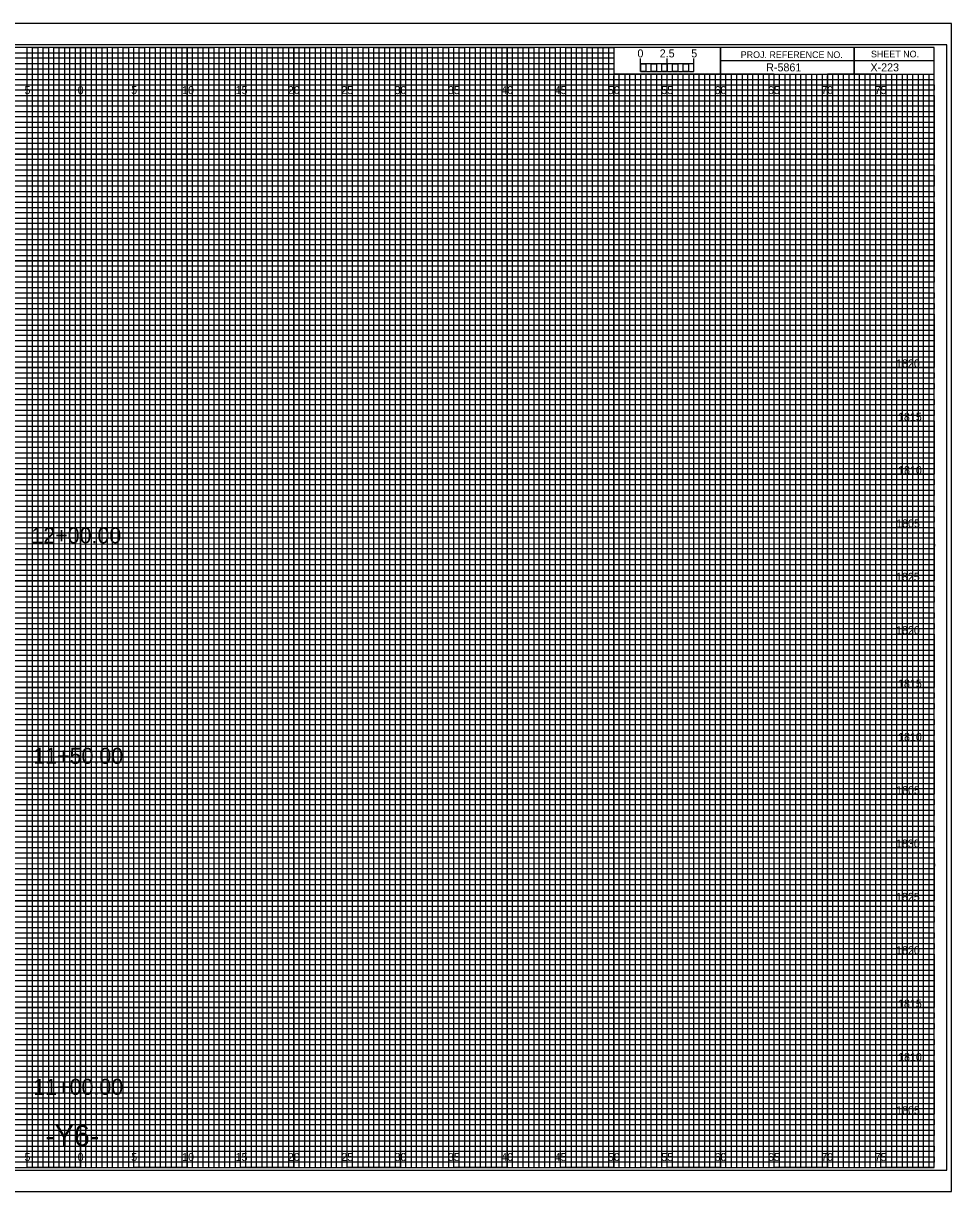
# Model space of a CAD drawing. Extents: x -7 to 392, y -2 to 440.
# Drawn here: x 74.6 to 161.6, y -2.3 to 107.3 of the extents above; entities that cross this region are included whole.
import ezdxf

# ---------------------------------------------------------------- set-up
doc = ezdxf.new("R2010")
doc.units = 0
for name, color, linetype in [('Prop Grid Mask', 7, 'Continuous'), ('Prop XS Alignment Label', 7, 'Continuous'), ('Prop XS Bar Scale Labels', 7, 'Continuous'), ('Prop XS Elevation Labels', 7, 'Continuous'), ('Prop XS Project Number', 7, 'Continuous'), ('Prop XS Sheet Number', 7, 'Continuous'), ('Prop XS Station Labels', 7, 'Continuous'), ('Sheet Cross Section CELL', 7, 'Continuous'), ('Sheet Cross Section Grid Major CELL', 7, 'Continuous'), ('Sheet Cross Section Grid Middle CELL', 7, 'Continuous'), ('Sheet Cross Section Grid Minor 1 CELL', 7, 'Continuous'), ('Sheet Cross Section Grid Minor 2 CELL', 7, 'Continuous'), ('Sheet Cross Section Scale CELL', 7, 'Continuous'), ('Sheet Cutting Line CELL', 7, 'Continuous'), ('Sheet DOT Grid CELL', 7, 'Continuous'), ('Sheet Plot Border Inside CELL', 7, 'Continuous'), ('Sheet Plot Border Outside CELL', 7, 'Continuous')]:
    doc.layers.add(name, color=color, linetype=linetype)

msp = doc.modelspace()

# ---------------------------------------------------------------- linework, layer by layer
at = {"layer": 'Sheet Cross Section CELL'}
for p, q in [((152.5, 105), (152.5, 102.5)), ((152.5, 102.5), (152.5, 105)), ((160, 103.75), (140, 103.75)), ((140, 103.75), (140, 102.5)), ((140, 102.5), (160, 102.5))]:
    msp.add_line(p, q, dxfattribs=at)
for points in [[(160, 105), (0, 105), (0, 0), (160, 0)], [(140, 105), (130, 105), (130, 102.52), (140, 102.52)], [(160, 105), (140, 105), (140, 102.5), (160, 102.5)]]:
    msp.add_lwpolyline(points, close=True, dxfattribs=at)
at = {"layer": 'Sheet Cross Section Grid Major CELL'}
for p, q in [((75, 105), (70, 105)), ((75, 0), (75, 105)), ((85, 105), (80, 105)), ((80, 105), (80, 0)), ((85, 0), (85, 105)), ((95, 105), (90, 105)), ((90, 105), (90, 0)), ((95, 0), (95, 105)), ((105, 105), (100, 105)), ((100, 105), (100, 0)), ((105, 0), (105, 105)), ((115, 105), (110, 105)), ((110, 105), (110, 0)), ((115, 0), (115, 105)), ((125, 105), (120, 105)), ((120, 105), (120, 0)), ((125, 0), (125, 105)), ((130, 105), (130, 0)), ((135, 0), (135, 102.5)), ((145, 102.5), (140, 102.5)), ((140, 102.5), (140, 0)), ((145, 0), (145, 102.5)), ((155, 102.5), (150, 102.5)), ((150, 102.5), (150, 0)), ((155, 0), (155, 102.5)), ((80, 0), (75, 0)), ((90, 0), (85, 0)), ((100, 0), (95, 0)), ((110, 0), (105, 0)), ((120, 0), (115, 0)), ((130, 0), (125, 0)), ((140, 0), (135, 0)), ((150, 0), (145, 0)), ((160, 0), (155, 0)), ((160, 0), (160, 0))]:
    msp.add_line(p, q, dxfattribs=at)
for points in [[(0, 100), (160, 100), (160, 95), (0, 95)], [(0, 90), (160, 90), (160, 85), (0, 85)], [(0, 80), (160, 80), (160, 75), (0, 75)], [(0, 70), (160, 70), (160, 65), (0, 65)], [(0, 60), (160, 60), (160, 55), (0, 55)], [(0, 50), (160, 50), (160, 45), (0, 45)], [(0, 40), (160, 40), (160, 35), (0, 35)], [(0, 30), (160, 30), (160, 25), (0, 25)], [(0, 20), (160, 20), (160, 15), (0, 15)], [(0, 10), (160, 10), (160, 5), (0, 5)]]:
    msp.add_lwpolyline(points, dxfattribs=at)
at = {"layer": 'Sheet Cross Section Grid Middle CELL'}
for points in [[(72.5, 0), (77.5, 0), (77.5, 105), (82.5, 105), (82.5, 0), (87.5, 0), (87.5, 105), (92.5, 105), (92.5, 0), (97.5, 0), (97.5, 105), (102.5, 105), (102.5, 0), (107.5, 0), (107.5, 105), (112.5, 105), (112.5, 0), (117.5, 0), (117.5, 105), (122.5, 105), (122.5, 0), (127.5, 0), (127.5, 105), (129.96, 105), (130, 105), (130, 102.5), (132.49, 102.5), (132.49, 0), (137.5, 0), (137.5, 102.5), (142.5, 102.5), (142.5, 0), (147.5, 0), (147.5, 102.5), (152.5, 102.5), (152.5, 0), (157.5, 0), (157.5, 102.5)], [(0, 102.5), (137.5, 102.5)], [(0, 92.5), (160, 92.5), (160, 97.5), (0, 97.5)], [(0, 82.5), (160, 82.5), (160, 87.5), (0, 87.5)], [(0, 72.5), (160, 72.5), (160, 77.5), (0, 77.5)], [(0, 62.5), (160, 62.5), (160, 67.5), (0, 67.5)], [(0, 52.5), (160, 52.5), (160, 57.5), (0, 57.5)], [(0, 42.5), (160, 42.5), (160, 47.5), (0, 47.5)], [(0, 32.5), (160, 32.5), (160, 37.5), (0, 37.5)], [(0, 22.5), (160, 22.5), (160, 27.5), (0, 27.5)], [(0, 12.5), (160, 12.5), (160, 17.5), (0, 17.5)], [(0, 2.5), (160, 2.5), (160, 7.5), (0, 7.5)]]:
    msp.add_lwpolyline(points, dxfattribs=at)
at = {"layer": 'Sheet Cross Section Grid Minor 1 CELL'}
for p, q in [((0, 104.5), (130, 104.5)), ((130, 104.5), (130, 103.99)), ((130, 103.99), (0, 103.99)), ((0, 103.5), (130, 103.5)), ((130, 102.95), (0, 102.95)), ((130, 103.5), (130, 102.95)), ((0, 102), (160, 102))]:
    msp.add_line(p, q, dxfattribs=at)
for points in [[(0, 101.5), (135, 101.5), (160, 101.5), (160, 101), (0, 101)], [(0, 100.5), (160, 100.5), (160, 99.5), (0, 99.5)], [(0, 99), (160, 99), (160, 98.5), (0, 98.49)], [(0, 98), (160, 98), (160, 97), (0, 97)], [(0, 96.5), (160, 96.5), (160, 96), (0, 96)], [(0, 95.5), (160, 95.5), (160, 94.5), (0, 94.5)], [(0, 94), (160, 94), (160, 93.5), (0, 93.5)], [(0, 93), (160, 93), (160, 92), (0, 92)], [(0, 91.5), (160, 91.5), (160, 91), (0, 91)], [(0, 90.5), (160, 90.5), (160, 89.5), (0, 89.5)], [(0, 89), (160, 89), (160, 88.5), (0, 88.5)], [(0, 88), (160, 88), (160, 86.98), (160, 86.5), (160, 86), (0, 86)], [(0, 87), (160, 87), (160, 86.5), (0, 86.5)], [(0, 85.5), (160, 85.5), (160, 84.5), (0, 84.52)], [(0, 84.52), (160, 84.5), (160, 84), (0, 84)], [(0, 83.5), (160, 83.5), (160, 83), (0, 83)], [(0, 82), (160, 82), (160, 81.5), (0, 81.5)], [(0, 81), (160, 81), (160, 80.5), (0, 80.5)], [(-0.04, 79.45), (160, 79.45), (160, 78.94), (-0.04, 78.94)], [(0, 78.5), (160, 78.5), (160, 78), (0, 78)], [(0, 77), (160, 77), (160, 76.5), (0, 76.5)], [(0, 76), (160, 76), (160, 75.5), (0, 75.5)], [(0, 74.5), (160, 74.5), (160, 74), (0, 74)], [(0, 73.5), (160, 73.5), (160, 73), (0, 73)], [(0, 72), (160, 72), (160, 71.5), (0, 71.5)], [(0, 71), (160, 71), (160, 70.5), (0, 70.5)], [(0, 69.5), (160, 69.5), (159.99, 68.99), (0, 69)], [(0, 68.5), (160, 68.5), (160, 68), (0, 68)], [(0, 67), (160, 67), (160, 66.5), (0, 66.5)], [(0, 66), (160, 66), (160, 65.5), (0, 65.5)], [(0, 64.5), (160, 64.5), (160, 64), (0, 64)], [(0, 63.5), (160, 63.5), (160, 63), (0, 63)], [(0, 62), (160, 62), (160, 61.5), (0, 61.5)], [(0, 61), (160, 61), (160, 60.5), (0, 60.5)], [(0, 59.5), (160, 59.5), (160, 59), (0, 59)], [(0, 58.5), (160.03, 58.45), (160, 58), (0, 58)], [(0, 57), (160, 57), (160, 56.5), (0, 56.5)], [(0, 56), (160, 56), (160, 55.5), (0, 55.5)], [(0, 54.5), (160, 54.5), (160, 54), (0, 54)], [(0, 53.5), (160, 53.5), (160, 53), (0, 53)], [(0, 52), (160, 52), (160, 51.5), (0, 51.5)], [(0, 51), (160, 51), (160, 50.5), (0, 50.5)], [(0, 49.5), (160, 49.5), (160, 49), (0, 49)], [(0, 48.5), (160, 48.5), (160, 48), (0, 48)], [(0, 47), (160, 47), (160, 46.5), (0, 46.5)], [(0, 46), (160, 46), (160, 45.5), (0, 45.5)], [(0, 44.5), (160, 44.5), (160, 44), (0, 44)], [(0, 43.5), (160, 43.5), (160, 43), (0, 43)], [(0, 42), (160, 42), (160, 41.5), (0, 41.5)], [(0, 41), (160, 41), (160, 40.5), (0, 40.5)], [(0, 39.5), (160, 39.5), (159.99, 38.99), (0, 39)], [(0, 38.5), (160, 38.5), (160, 38), (0, 38)], [(0, 37), (160, 37), (160, 36.5), (0, 36.5)], [(0, 36), (160, 36), (160, 35.5), (0, 35.5)], [(0, 34.5), (160, 34.5), (160, 34), (0, 34)], [(0, 33.5), (160, 33.5), (160, 33), (0, 33)], [(0, 32), (160, 32), (160, 31.5), (0, 31.5)], [(0, 31), (160, 31), (160, 30.5), (0, 30.5)], [(0, 29.5), (160, 29.5), (160, 29), (0, 29)], [(0, 28.5), (160.03, 28.46), (160, 28), (0, 28)], [(0, 27), (160, 27), (160, 26.5), (0, 26.5)], [(0, 26), (160, 26), (160, 25.5), (0, 25.5)], [(0, 24.5), (160, 24.5), (160, 24), (0, 24)], [(0, 23.5), (160, 23.5), (160, 23), (0, 23)], [(0, 22), (160, 22), (160, 21.5), (0, 21.5)], [(0, 21), (160, 21), (160, 20.5), (0, 20.5)], [(0, 19.5), (160, 19.5), (160, 19), (0, 19)], [(0, 18.5), (160, 18.5), (160, 18), (0, 18)], [(0, 17), (160, 17), (160, 16.5), (0, 16.5)], [(0, 16), (160, 16), (160, 15.5), (0, 15.5)], [(0, 14.5), (160, 14.5), (160, 14), (0, 14)], [(0, 13.5), (160, 13.5), (160, 13), (0, 13)], [(0, 12), (160, 12), (160, 11.5), (0, 11.5)], [(0, 11), (160, 11), (160, 10.5), (0, 10.5)], [(0, 9.5), (160, 9.5), (160, 9), (0, 9)], [(0, 8.5), (160, 8.5), (160, 8), (0, 8)], [(0, 7), (160, 7), (160, 6.5), (0, 6.5)], [(0, 6), (160, 6), (160, 5.5), (0, 5.5)], [(0, 4.5), (160, 4.5), (160, 4), (0, 4)], [(0, 3.5), (160, 3.5), (160, 3), (0, 3)], [(0, 2), (160, 2), (160, 1.5), (0, 1.5)], [(0, 1), (160, 1), (160, 0.5), (0, 0.5)]]:
    msp.add_lwpolyline(points, dxfattribs=at)
at = {"layer": 'Sheet Cross Section Grid Minor 2 CELL'}
for p, q in [((133.5, 102.5), (133, 102.5)), ((133, 102.5), (133, 0)), ((133.5, 0), (133.5, 102.5)), ((134.5, 102.5), (134, 102.5)), ((134, 102.5), (134, 0)), ((134.5, 0), (134.5, 102.5)), ((133, 0), (132.5, 0)), ((134, 0), (133.5, 0))]:
    msp.add_line(p, q, dxfattribs=at)
for points in [[(75, 0), (75.5, 0), (75.5, 105), (76, 105), (76, 0)], [(76, 0), (76.5, 0), (76.5, 105), (77, 105), (77, 0)], [(77.5, 0), (78, 0), (78, 105), (78.5, 105), (78.5, 0)], [(78.5, 0), (79, 0), (79, 105), (79.5, 105), (79.5, 0)], [(80, 0), (80.5, 0), (80.5, 105), (81, 105), (81, 0)], [(81, 0), (81.5, 0), (81.5, 105), (82, 105), (82, 0)], [(82.5, 0), (83, 0), (83, 105), (83.5, 105), (83.5, 0)], [(83.5, 0), (84, 0), (84, 105), (84.5, 105), (84.5, 0)], [(85, 0), (85.5, 0), (85.5, 105), (86, 105), (86, 0)], [(86, 0), (86.5, 0), (86.5, 105), (87, 105), (87, 0)], [(87.5, 0), (88, 0), (88, 105), (88.5, 105), (88.5, 0)], [(88.5, 0), (89, 0), (89, 105), (89.5, 105), (89.5, 0)], [(90, 0), (90.5, 0), (90.5, 105), (91, 105), (91, 0)], [(91, 0), (91.5, 0), (91.5, 105), (92, 105), (92, 0)], [(92.5, 0), (93, 0), (93, 105), (93.5, 105), (93.5, 0)], [(93.5, 0), (94, 0), (94, 105), (94.5, 105), (94.5, 0)], [(95, 0), (95.5, 0), (95.5, 105), (96, 105), (96, 0)], [(96, 0), (96.5, 0), (96.5, 105), (97, 105), (97, 0)], [(97.5, 0), (98, 0), (98, 105), (98.5, 105), (98.5, 0)], [(98.5, 0), (99, 0), (99, 105), (99.5, 105), (99.5, 0)], [(100, 0), (100.5, 0), (100.5, 105), (101, 105), (101, 0)], [(101, 0), (101.5, 0), (101.5, 105), (102, 105), (102, 0)], [(102.5, 0), (103, 0), (103, 105), (103.5, 105), (103.5, 0)], [(103.5, 0), (104, 0), (104, 105), (104.5, 105), (104.5, 0)], [(105, 0), (105.5, 0), (105.5, 105), (106, 105), (106, 0)], [(106, 0), (106.5, 0), (106.5, 105), (107, 105), (107, 0)], [(107.5, 0), (108, 0), (108, 105), (108.5, 105), (108.5, 0)], [(108.5, 0), (109, 0), (109, 105), (109.5, 105), (109.5, 0)], [(110, 0), (110.5, 0), (110.5, 105), (111, 105), (111, 0)], [(111, 0), (111.5, 0), (111.5, 105), (112, 105), (112, 0)], [(112.5, 0), (113, 0), (113, 105), (113.5, 105), (113.5, 0)], [(113.5, 0), (114, 0), (114, 105), (114.5, 105), (114.5, 0)], [(115, 0), (115.5, 0), (115.5, 105), (116, 105), (116, 0)], [(116, 0), (116.5, 0), (116.5, 105), (117, 105), (117, 0)], [(117.5, 0), (118, 0), (118, 105), (118.5, 105), (118.5, 0)], [(118.5, 0), (119, 0), (119, 105), (119.5, 105), (119.5, 0)], [(120, 0), (120.5, 0), (120.5, 105), (121, 105), (121, 0)], [(121, 0), (121.5, 0), (121.5, 105), (122, 105), (122, 0)], [(122.5, 0), (123, 0), (123, 105), (123.5, 105), (123.5, 0)], [(123.5, 0), (124, 0), (124, 105), (124.5, 105), (124.5, 0)], [(125, 0), (125.5, 0), (125.5, 105), (126, 105), (126, 0)], [(126, 0), (126.5, 0), (126.5, 105), (127, 105), (127, 0)], [(127.5, 0), (128, 0), (128, 105), (128.5, 105), (128.5, 0)], [(128.5, 0), (129, 0), (129, 105), (129.5, 105), (129.5, 0)], [(130, 0), (130.5, 0), (130.5, 102.5), (131.01, 102.5), (131.01, 0)], [(131, 0), (131.5, 0), (131.5, 102.5), (131.99, 102.5), (131.99, 0)], [(135, 0), (135.49, 0), (135.49, 102.5), (136, 102.5), (136, 0)], [(136, 0), (136.5, 0), (136.5, 102.5), (137.02, 102.5), (137.02, 0)], [(137.5, 0), (138, 0), (138, 102.5), (138.5, 102.5), (138.5, 0)], [(138.5, 0), (139, 0), (139, 102.5), (139.5, 102.5), (139.5, 0)], [(140, 0), (140.5, 0), (140.5, 102.5), (141, 102.5), (141, 0)], [(141, 0), (141.5, 0), (141.5, 102.5), (142, 102.5), (142, 0)], [(142.5, 0), (143, 0), (143, 102.5), (143.5, 102.5), (143.5, 0)], [(143.5, 0), (144, 0), (144, 102.5), (144.5, 102.5), (144.5, 0)], [(145, 0), (145.5, 0), (145.5, 102.5), (146, 102.5), (146, 0)], [(146, 0), (146.5, 0), (146.5, 102.5), (147, 102.5), (147, 0)], [(147.5, 0), (148, 0), (148, 102.5), (148.5, 102.5), (148.5, 0)], [(148.5, 0), (149, 0), (149, 102.5), (149.5, 102.5), (149.5, 0)], [(150, 0), (150.5, 0), (150.5, 102.5), (151, 102.5), (151, 0)], [(151, 0), (151.5, 0), (151.5, 102.5), (152, 102.5), (152, 0)], [(152.5, 0), (153, 0), (153, 102.5), (153.5, 102.5), (153.5, 0)], [(153.5, 0), (154, 0), (154, 102.5), (154.5, 102.5), (154.5, 0)], [(155, 0), (155.5, 0), (155.5, 102.5), (156, 102.5), (156, 0)], [(156, 0), (156.5, 0), (156.5, 102.5), (157, 102.5), (157, 0)], [(157.5, 0), (158, 0), (158, 102.5), (158.5, 102.5), (158.5, 0)], [(158.5, 0), (159, 0), (159, 102.5), (159.5, 102.5), (159.5, 0)]]:
    msp.add_lwpolyline(points, dxfattribs=at)
at = {"layer": 'Sheet Cross Section Scale CELL'}
for p, q in [((132.5, 102.75), (132.5, 103.95)), ((132.5, 103.45), (132.5, 103.95)), ((135, 102.75), (135, 103.95)), ((137.5, 102.75), (137.5, 103.95)), ((137.5, 103.45), (137.5, 103.95))]:
    msp.add_line(p, q, dxfattribs=at)
for points in [[(137.5, 103.45), (132.5, 103.45), (132.5, 102.75), (137.5, 102.75)], [(132.5, 103.45), (133, 103.45), (133, 102.75), (132.5, 102.75)], [(133.5, 103.45), (134, 103.45), (134, 102.75), (133.5, 102.75)], [(134.5, 103.45), (135, 103.45), (135, 102.75), (134.5, 102.75)], [(135.5, 103.45), (136, 103.45), (136, 102.75), (135.5, 102.75)], [(136.5, 103.45), (137, 103.45), (137, 102.75), (136.5, 102.75)]]:
    msp.add_lwpolyline(points, close=True, dxfattribs=at)
at = {"layer": 'Sheet Cutting Line CELL'}
for p, q in [((161.65, 107.25), (-6.7, 107.25)), ((-6.7, -2.25), (161.65, -2.25))]:
    msp.add_line(p, q, dxfattribs=at)
at = {"layer": 'Sheet DOT Grid CELL'}
for p, q in [((75, 0), (75, 105)), ((80, 0), (80, 105)), ((85, 0), (85, 105)), ((90, 0), (90, 105)), ((95, 0), (95, 105)), ((100, 0), (100, 105)), ((105, 0), (105, 105)), ((110, 0), (110, 105)), ((115, 0), (115, 105)), ((120, 0), (120, 105)), ((125, 0), (125, 105)), ((130, 0), (130, 102.34)), ((135, 0), (135, 102.34)), ((140, 0), (140, 102.34)), ((145, 0), (145, 102.34)), ((150, 0), (150, 102.34)), ((155, 0), (155, 102.34)), ((0, 100), (160, 100)), ((0, 95), (160, 95)), ((0, 90), (160, 90)), ((0, 85), (160, 85)), ((0, 80), (160, 80)), ((0, 75), (160, 75)), ((0, 70), (160, 70)), ((0, 65), (160, 65)), ((0, 60), (160, 60)), ((0, 55), (160, 55)), ((0, 50), (160, 50)), ((0, 45), (160, 45)), ((0, 40), (160, 40)), ((0, 35), (160, 35)), ((0, 30), (160, 30)), ((0, 25), (160, 25)), ((0, 20), (160, 20)), ((0, 15), (160, 15)), ((0, 10), (160, 10)), ((0, 5), (160, 5))]:
    msp.add_line(p, q, dxfattribs=at)
at = {"layer": 'Sheet Plot Border Inside CELL'}
msp.add_lwpolyline([(-5.4, -0.25), (161.2, -0.25), (161.2, 105.25), (-5.4, 105.25)], close=True, dxfattribs=at)
at = {"layer": 'Sheet Plot Border Outside CELL'}
msp.add_lwpolyline([(-6.7, -2.25), (161.65, -2.25), (161.65, 107.25), (-6.7, 107.25)], close=True, dxfattribs=at)

# ---------------------------------------------------------------- texts
at = {"layer": 'Prop Grid Mask'}
for s, p in [('5', (74.74, 100.62)), ('0', (79.73, 100.62)), ('0', (79.73, 100.62)), ('5', (84.74, 100.62)), ('10', (89.52, 100.62)), ('15', (94.53, 100.62)), ('20', (99.43, 100.62)), ('25', (104.44, 100.62)), ('30', (109.43, 100.62)), ('35', (114.44, 100.62)), ('40', (119.43, 100.62)), ('45', (124.44, 100.62)), ('50', (129.43, 100.62)), ('55', (134.44, 100.62)), ('60', (139.43, 100.62)), ('65', (144.44, 100.62)), ('70', (149.43, 100.62)), ('75', (154.44, 100.62)), ('5', (74.74, 0.62)), ('0', (79.73, 0.62)), ('0', (79.73, 0.62)), ('5', (84.74, 0.62)), ('10', (89.52, 0.62)), ('15', (94.53, 0.62)), ('20', (99.43, 0.62)), ('25', (104.44, 0.62)), ('30', (109.43, 0.62)), ('35', (114.44, 0.62)), ('40', (119.43, 0.62)), ('45', (124.44, 0.62)), ('50', (129.43, 0.62)), ('55', (134.44, 0.62)), ('60', (139.43, 0.62)), ('65', (144.44, 0.62)), ('70', (149.43, 0.62)), ('75', (154.44, 0.62))]:
    msp.add_text(s, height=0.75, dxfattribs=at).set_placement(p)
at = {"layer": 'Prop XS Alignment Label'}
msp.add_text('-Y6-', height=2, dxfattribs=at).set_placement((76.7, 2))
at = {"layer": 'Prop XS Bar Scale Labels'}
for s, p in [('2.5', (134.29, 104.06)), ('5', (137.24, 104.06))]:
    msp.add_text(s, height=0.75, dxfattribs=at).set_placement(p)
at = {"layer": 'Prop XS Elevation Labels'}
for s, p in [('1820', (156.44, 75)), ('1815', (156.62, 70)), ('1810', (156.63, 65)), ('1805', (156.45, 60)), ('1825', (156.43, 55)), ('1820', (156.44, 50)), ('1815', (156.62, 45)), ('1810', (156.63, 40)), ('1805', (156.45, 35)), ('1830', (156.43, 30)), ('1825', (156.43, 25)), ('1820', (156.44, 20)), ('1815', (156.62, 15)), ('1810', (156.63, 10)), ('1805', (156.45, 5))]:
    msp.add_text(s, height=0.75, dxfattribs=at).set_placement(p)
at = {"layer": 'Prop XS Project Number'}
msp.add_text('R-5861', height=0.75, dxfattribs=at).set_placement((144.27, 102.75))
at = {"layer": 'Prop XS Sheet Number'}
msp.add_text('X-223', height=0.75, dxfattribs=at).set_placement((154.04, 102.75))
at = {"layer": 'Prop XS Station Labels'}
for s, p in [('12+00.00', (75.39, 58.51)), ('11+50.00', (75.57, 37.85)), ('11+00.00', (75.57, 6.82))]:
    msp.add_text(s, height=1.5, dxfattribs=at).set_placement(p)
at = {"layer": 'Sheet Cross Section CELL'}
for s, p in [('PROJ. REFERENCE NO.', (141.88, 104)), ('SHEET NO.', (154.09, 104.06))]:
    msp.add_text(s, height=0.625, dxfattribs=at).set_placement(p)
at = {"layer": 'Sheet Cross Section Scale CELL'}
msp.add_text('0', height=0.75, dxfattribs=at).set_placement((132.2, 104.06))

doc.saveas('drawing.dxf')
